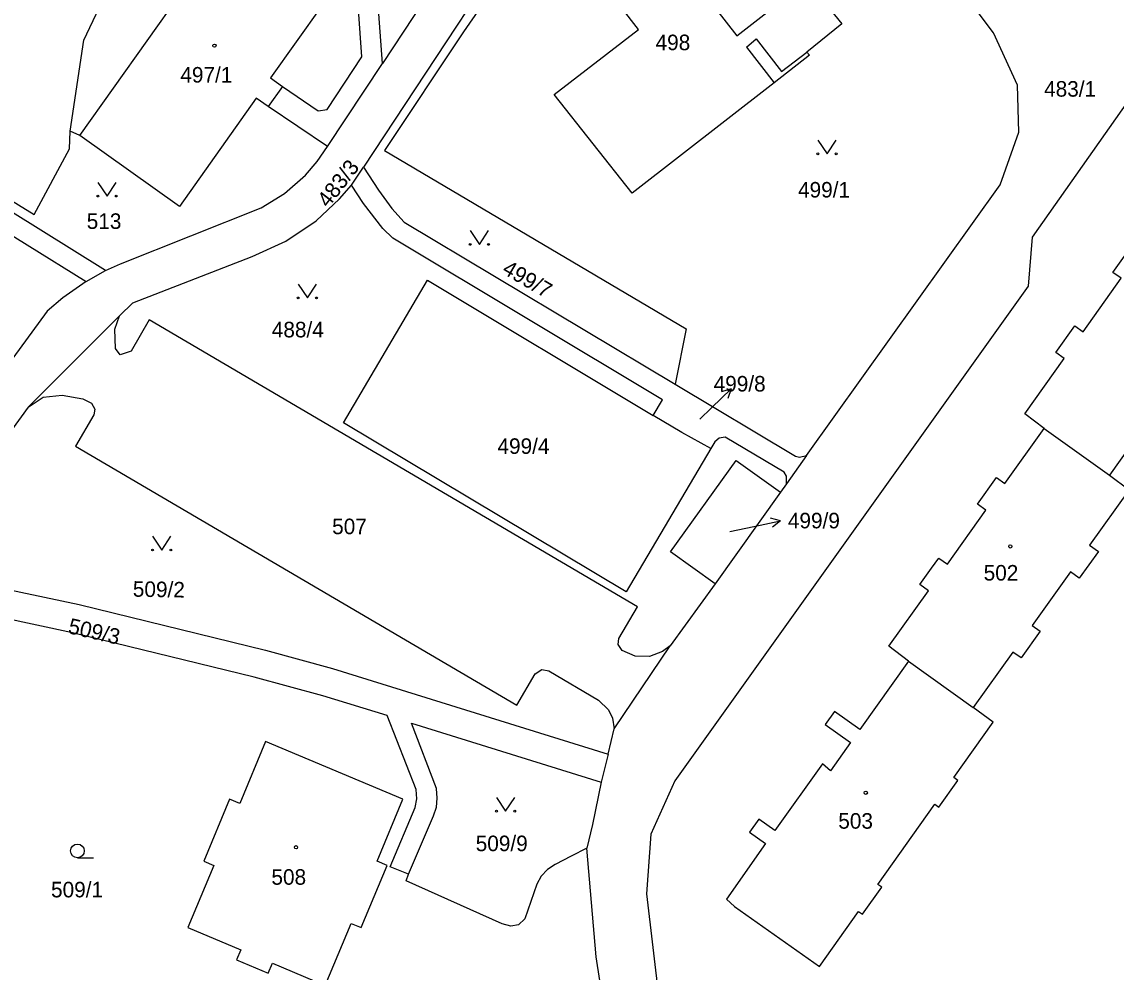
# Model space of a CAD drawing. Extents: x -558500 to -557517, y -1073973 to -1073051.
# Drawn here: x -558029.6 to -557909.9, y -1073540.5 to -1073436.6 of the extents above; entities that cross this region are included whole.
import ezdxf

# ---------------------------------------------------------------- set-up
doc = ezdxf.new("R2010")
doc.units = 0
for name, color, linetype in [('Hranice parcel', 7, 'Continuous'), ('Parcelní čísla', 7, 'Continuous'), ('Pop  PČ popisy', 7, 'Continuous'), ('Vnitřní kresba', 7, 'Continuous'), ('Značky budov', 7, 'Continuous'), ('Značky kultur', 7, 'Continuous')]:
    doc.layers.add(name, color=color, linetype=linetype)

msp = doc.modelspace()

# ---------------------------------------------------------------- linework, layer by layer
at = {"layer": 'Hranice parcel'}
for p, q in [((-557996.12, -1073450.19), (-557990.11, -1073441.11)), ((-558001.05, -1073443.62), (-558002.62, -1073445.83)), ((-558001.05, -1073443.62), (-557997.16, -1073446.28)), ((-557996.12, -1073450.19), (-558002.62, -1073445.83)), ((-558023.22, -1073448.98), (-558024.27, -1073448.53)), ((-557993.5, -1073454.4), (-557992.19, -1073452.45)), ((-557987.76, -1073458.45), (-557958.11, -1073476.19)), ((-558022.54, -1073464.96), (-558020.42, -1073463.73)), ((-558018.89, -1073468.72), (-558028.88, -1073478.68)), ((-557958.11, -1073476.19), (-557944.96, -1073484.06)), ((-557917.76, -1073481.02), (-557910.62, -1073486.13)), ((-557958.62, -1073494.5), (-557951.44, -1073484.51)), ((-557951.44, -1073484.51), (-557946.6, -1073487.99)), ((-557943.74, -1073483.99), (-557945.94, -1073487.07)), ((-557944.96, -1073484.06), (-557944.51, -1073484.17)), ((-557944.51, -1073484.17), (-557943.74, -1073483.99)), ((-557945.94, -1073487.07), (-557946.6, -1073487.99)), ((-557945.94, -1073487.07), (-557945.95, -1073486.25)), ((-557946.6, -1073487.99), (-557953.75, -1073497.99)), ((-557953.75, -1073497.99), (-557958.62, -1073494.5)), ((-557953.75, -1073497.99), (-557958.67, -1073504.77)), ((-557964.79, -1073513.87), (-557958.67, -1073504.77)), ((-557932.61, -1073506.45), (-557925.51, -1073511.53)), ((-557965.43, -1073516.64), (-557964.79, -1073513.87)), ((-557965.43, -1073516.64), (-557966.22, -1073519.7)), ((-557966.22, -1073519.7), (-557967.17, -1073524.31)), ((-557967.17, -1073524.31), (-557967.76, -1073526.9)), ((-557967.76, -1073526.9), (-557969.49, -1073527.78))]:
    msp.add_line(p, q, dxfattribs=at)
for points in [[(-557997.16, -1073446.28), (-557996.18, -1073446.14), (-557992.37, -1073440.37), (-557993.13, -1073429.99), (-557993.58, -1073428.02), (-558004.25, -1073395), (-558005.55, -1073391.58), (-558006.57, -1073389.94), (-558009.69, -1073386.81), (-558015.69, -1073381.13), (-558022.86, -1073375.1), (-558038.38, -1073364.54), (-558051.46, -1073355.75)], [(-557990.11, -1073441.11), (-557990.95, -1073429.72), (-557991.6, -1073426.99), (-558000.34, -1073399.97), (-557986.42, -1073409.86), (-557979.13, -1073399.38), (-557977.23, -1073400.7), (-557975.75, -1073398.59), (-557966.19, -1073404.96)], [(-557943.74, -1073483.99), (-557922.57, -1073454.37), (-557920.54, -1073448.62), (-557920.67, -1073443.5), (-557923.32, -1073437.76), (-557933.57, -1073424.07), (-557935, -1073422.19), (-557950.81, -1073400.97)], [(-557966.19, -1073404.96), (-557967.15, -1073406.3), (-557970.9, -1073403.86), (-557989.34, -1073431.82), (-557985.62, -1073434.28), (-557990.11, -1073441.11)], [(-557960.73, -1073418.81), (-557955.07, -1073414.41), (-557951.22, -1073411.42), (-557950.93, -1073411.8), (-557947.21, -1073416.59), (-557951.08, -1073419.63), (-557946.63, -1073425.3), (-557955.8, -1073432.39), (-557951.37, -1073438.08), (-557947.44, -1073435.04), (-557943.73, -1073432.04), (-557939.89, -1073436.78), (-557943.7, -1073439.86), (-557943.42, -1073440.21), (-557947.29, -1073443.23), (-557962.81, -1073455.3), (-557971.36, -1073444.52), (-557962.13, -1073437.38), (-557970.6, -1073426.47), (-557970.03, -1073426.04)], [(-557875.08, -1073418.52), (-557880.11, -1073415), (-557884.66, -1073414.11), (-557888.78, -1073417.07), (-557919.08, -1073460.09), (-557919.51, -1073465.45), (-557958.15, -1073519.56), (-557960.76, -1073525.37), (-557961.25, -1073531.9), (-557959.85, -1073543.64), (-557958.52, -1073546.41), (-557955.67, -1073549.33), (-557941.9, -1073559.58)], [(-557968.81, -1073419.39), (-557969.8, -1073419.14), (-557970.66, -1073419.77), (-557992.19, -1073452.45)], [(-558023.22, -1073448.98), (-558004.82, -1073423.06), (-557993.94, -1073430.83), (-558002.36, -1073442.69), (-558001.05, -1073443.62)], [(-557971.99, -1073423.64), (-557977.49, -1073432.15), (-557981.25, -1073437.64), (-557989.89, -1073450.63)], [(-558024.27, -1073448.53), (-558022.77, -1073438.58), (-558021.1, -1073435.02), (-558027.22, -1073431.17)], [(-558063.79, -1073443.12), (-558051.12, -1073443.51), (-558028.21, -1073457.62), (-558024.35, -1073450.45), (-558024.27, -1073448.53)], [(-558020.42, -1073463.73), (-558041.1, -1073450.88), (-558045.53, -1073448.61), (-558050.06, -1073446.9), (-558053.87, -1073445.77), (-558058.84, -1073444.97), (-558063.8, -1073444.57)], [(-558002.62, -1073445.83), (-558003.93, -1073444.91), (-558012.33, -1073456.75), (-558023.22, -1073448.98)], [(-558063.26, -1073446.76), (-558059.34, -1073447.1), (-558054.18, -1073447.94), (-558050.82, -1073448.92), (-558046.65, -1073450.5), (-558041.92, -1073452.93), (-558022.54, -1073464.96)], [(-558020.42, -1073463.73), (-558018.76, -1073463.03), (-558003.4, -1073456.89), (-558000.84, -1073455.32), (-557998.53, -1073453.34), (-557997.26, -1073451.83), (-557996.12, -1073450.19)], [(-557989.89, -1073450.63), (-557956.91, -1073470.13), (-557958.11, -1073476.19)], [(-557992.19, -1073452.45), (-557990.57, -1073454.98), (-557989.11, -1073456.98), (-557987.76, -1073458.45)], [(-558018.89, -1073468.72), (-558017.43, -1073467.28), (-558004.36, -1073462.2), (-558000.71, -1073460.54), (-557997.38, -1073458.33), (-557994.81, -1073455.9), (-557993.5, -1073454.4)], [(-557960.53, -1073479.61), (-557959.52, -1073477.88), (-557988.99, -1073460.22), (-557990.09, -1073459.14), (-557992.19, -1073456.42), (-557993.5, -1073454.4)], [(-557917.76, -1073481.02), (-557919.89, -1073479.42), (-557915.58, -1073473.37), (-557916.49, -1073472.72), (-557914.4, -1073469.79), (-557913.49, -1073470.44), (-557909.33, -1073464.6), (-557910.24, -1073463.95), (-557908.96, -1073462.17), (-557908.15, -1073461.02), (-557907.24, -1073461.67), (-557902.93, -1073455.63)], [(-557895.8, -1073460.74), (-557893.65, -1073462.39), (-557897.97, -1073468.43), (-557896.94, -1073469.17), (-557899.02, -1073472.08), (-557900.05, -1073471.34), (-557904.22, -1073477.17), (-557903.16, -1073477.93), (-557905.25, -1073480.84), (-557906.3, -1073480.09), (-557910.62, -1073486.13)], [(-558022.54, -1073464.96), (-558025.08, -1073466.74), (-558026.8, -1073468.19), (-558032.65, -1073476.17)], [(-557954.23, -1073483.22), (-557963.48, -1073498.87), (-557994.38, -1073480.4), (-557985.2, -1073464.81), (-557960.53, -1073479.61)], [(-557958.67, -1073504.77), (-557959.52, -1073505.42), (-557960.94, -1073505.97), (-557962.48, -1073505.9), (-557963.93, -1073505.3), (-557964.34, -1073504.64), (-557964.29, -1073503.98), (-557962.25, -1073500.52), (-558015.64, -1073469.14), (-558017.62, -1073472.56), (-558018.8, -1073472.98), (-558019.32, -1073472.29), (-558019.38, -1073470.18), (-558018.89, -1073468.72)], [(-558028.88, -1073478.68), (-558027.22, -1073477.58), (-558025.14, -1073477.37), (-558022.91, -1073477.77), (-558021.94, -1073478.27), (-558021.58, -1073478.9), (-558021.69, -1073479.54), (-558023.7, -1073482.95), (-557975.42, -1073511.29), (-557973.41, -1073507.84), (-557972.71, -1073507.36), (-557971.95, -1073507.53), (-557966.49, -1073510.72), (-557965.39, -1073511.77), (-557964.96, -1073512.7), (-557964.79, -1073513.87)], [(-558028.88, -1073478.68), (-558041.38, -1073495.88), (-558041.79, -1073496.35)], [(-557954.23, -1073483.22), (-557957.38, -1073481.46), (-557960.53, -1073479.61)], [(-557932.61, -1073506.45), (-557934.75, -1073504.84), (-557930.41, -1073498.76), (-557931.35, -1073498.09), (-557930.07, -1073496.31), (-557929.28, -1073495.19), (-557928.34, -1073495.86), (-557924.14, -1073489.96), (-557925.07, -1073489.3), (-557922.99, -1073486.39), (-557922.06, -1073487.05), (-557917.76, -1073481.02)], [(-557945.95, -1073486.25), (-557946.2, -1073485.81), (-557952.65, -1073481.96), (-557953.3, -1073482.07), (-557953.78, -1073482.47), (-557954.23, -1073483.22)], [(-557910.62, -1073486.13), (-557908.48, -1073487.72), (-557912.81, -1073493.77), (-557911.82, -1073494.47), (-557913.92, -1073497.39), (-557914.9, -1073496.69), (-557919.09, -1073502.55), (-557918.19, -1073503.19), (-557920.29, -1073506.11), (-557921.18, -1073505.47), (-557925.51, -1073511.53)], [(-558041.79, -1073496.35), (-558023.3, -1073500.28), (-558002.91, -1073505.27), (-557995.6, -1073507.26), (-557965.43, -1073516.64)], [(-557987.27, -1073529.77), (-557989.29, -1073528.94), (-557986.56, -1073522.48), (-557986.36, -1073521.52), (-557986.44, -1073520.51), (-557989.6, -1073512.4), (-557996.64, -1073510.25), (-558004.14, -1073508.22), (-558024.01, -1073503.35), (-558039.66, -1073500.03), (-558040.64, -1073500.03), (-558041.42, -1073500.4), (-558042.23, -1073501), (-558043.97, -1073502.01), (-558045.84, -1073502.74), (-558047.8, -1073503.22), (-558050.8, -1073503.37), (-558053.79, -1073503.03), (-558062.52, -1073500.9), (-558063.99, -1073500.68), (-558064.96, -1073500.91), (-558065.77, -1073501.48), (-558066.28, -1073502.33), (-558068.72, -1073511.63)], [(-557932.61, -1073506.45), (-557937.92, -1073513.94), (-557940.69, -1073511.97), (-557941.71, -1073513.4), (-557938.93, -1073515.37), (-557941.12, -1073518.46), (-557942.01, -1073517.7), (-557947.21, -1073524.97), (-557948.97, -1073523.73), (-557949.99, -1073525.17), (-557948.24, -1073526.41), (-557952.49, -1073532.47), (-557951.63, -1073533.27), (-557942.33, -1073539.86), (-557938.05, -1073533.83), (-557937.62, -1073534.14), (-557935.52, -1073531.19), (-557935.95, -1073530.88), (-557929.72, -1073522.11), (-557929.27, -1073522.43), (-557927.19, -1073519.5), (-557927.64, -1073519.19), (-557923.33, -1073513.13), (-557925.51, -1073511.53)], [(-557987.27, -1073529.77), (-557984.55, -1073523.36), (-557984.23, -1073522.42), (-557984.14, -1073521.45), (-557984.2, -1073520.39), (-557986.94, -1073513.23), (-557966.22, -1073519.7)], [(-558008.57, -1073528.8), (-558011.42, -1073535.59), (-558005.63, -1073538.02), (-558006.1, -1073539.13), (-558002.62, -1073540.59), (-558002.16, -1073539.49), (-557996.41, -1073541.91), (-557993.56, -1073535.14), (-557992.45, -1073535.6), (-557989.61, -1073528.81), (-557990.71, -1073528.34), (-557987.91, -1073521.54), (-558002.9, -1073515.24), (-558005.74, -1073522.02), (-558006.84, -1073521.56), (-558009.68, -1073528.33), (-558008.57, -1073528.8)], [(-557969.49, -1073527.78), (-557971.24, -1073528.71), (-557972.09, -1073529.24), (-557972.78, -1073529.97), (-557973.26, -1073530.86), (-557974.57, -1073534.63), (-557975.26, -1073535.31), (-557976.1, -1073535.45), (-557977.05, -1073535.17), (-557987.55, -1073530.47), (-557987.27, -1073529.77)], [(-557961.12, -1073576.24), (-557962.13, -1073568.62), (-557962.94, -1073563.5), (-557966.76, -1073538.79), (-557967.76, -1073526.9)]]:
    msp.add_lwpolyline(points, dxfattribs=at)
at = {"layer": 'Pop  PČ popisy'}
for p, q in [((-557954.15, -1073478.76), (-557951.99, -1073476.68)), ((-557951.99, -1073476.68), (-557953.06, -1073477.01)), ((-557951.99, -1073476.68), (-557952.36, -1073477.73)), ((-557955.41, -1073479.99), (-557954.15, -1073478.76)), ((-557946.59, -1073491.11), (-557947.68, -1073490.82)), ((-557952.15, -1073492.28), (-557949.53, -1073491.73)), ((-557949.53, -1073491.73), (-557946.59, -1073491.11)), ((-557946.59, -1073491.11), (-557947.47, -1073491.8))]:
    msp.add_line(p, q, dxfattribs=at)
at = {"layer": 'Vnitřní kresba'}
for p, q in [((-557950.33, -1073439.32), (-557949.26, -1073438.42)), ((-557950.33, -1073439.32), (-557947.29, -1073443.23)), ((-557949.26, -1073438.42), (-557946.5, -1073442)), ((-557946.5, -1073442), (-557943.7, -1073439.86))]:
    msp.add_line(p, q, dxfattribs=at)
at = {"layer": 'Značky budov'}
for centre in [(-558008.5, -1073439.16), (-557921.47, -1073493.92), (-557937.27, -1073520.85), (-557999.58, -1073526.81)]:
    msp.add_circle(centre, 0.175, dxfattribs=at)
at = {"layer": 'Značky kultur'}
msp.add_line((-558023.49, -1073527.96), (-558021.74, -1073527.96), dxfattribs=at)
for points in [[(-557942.51, -1073449.49), (-557941.51, -1073450.99), (-557940.51, -1073449.49)], [(-558021.24, -1073454.11), (-558020.24, -1073455.61), (-558019.24, -1073454.11)], [(-557980.53, -1073459.39), (-557979.53, -1073460.89), (-557978.53, -1073459.39)], [(-557999.34, -1073465.25), (-557998.34, -1073466.75), (-557997.34, -1073465.25)], [(-558015.26, -1073492.81), (-558014.26, -1073494.31), (-558013.26, -1073492.81)], [(-557977.66, -1073521.36), (-557976.66, -1073522.86), (-557975.66, -1073521.36)]]:
    msp.add_lwpolyline(points, dxfattribs=at)
for centre, radius in [((-557942.51, -1073450.99), 0.1), ((-557940.51, -1073450.99), 0.1), ((-558021.24, -1073455.61), 0.1), ((-558019.24, -1073455.61), 0.1), ((-557980.53, -1073460.89), 0.1), ((-557978.53, -1073460.89), 0.1), ((-557999.34, -1073466.75), 0.1), ((-557997.34, -1073466.75), 0.1), ((-558015.26, -1073494.31), 0.1), ((-558013.26, -1073494.31), 0.1), ((-557977.66, -1073522.86), 0.1), ((-557975.66, -1073522.86), 0.1), ((-558023.49, -1073527.21), 0.75)]:
    msp.add_circle(centre, radius, dxfattribs=at)

# ---------------------------------------------------------------- texts
at = {"layer": 'Parcelní čísla'}
for s, p in [('498', (-557960.26, -1073439.66)), ('497/1', (-558012.23, -1073443.2)), ('483/1', (-557917.77, -1073444.74)), ('499/1', (-557944.68, -1073455.77)), ('513', (-558022.47, -1073459.2)), ('488/4', (-558002.23, -1073471.06)), ('499/8', (-557953.91, -1073476.98)), ('499/4', (-557977.55, -1073483.8)), ('507', (-557995.63, -1073492.58)), ('499/9', (-557945.79, -1073491.94)), ('502', (-557924.38, -1073497.65)), ('503', (-557940.28, -1073524.78)), ('509/9', (-557979.93, -1073527.24)), ('508', (-558002.27, -1073530.91)), ('509/1', (-558026.37, -1073532.29))]:
    msp.add_text(s, height=1.7, dxfattribs=at).set_placement(p)
for s, rotation, p in [('483/3', 52, (-557996.07, -1073456.97)), ('499/7', 330, (-557977.15, -1073463.99)), ('509/2', 359, (-558017.44, -1073499.41)), ('509/3', 347, (-558024.6, -1073503.39))]:
    msp.add_text(s, height=1.7, rotation=rotation, dxfattribs=at).set_placement(p)

doc.saveas('drawing.dxf')
